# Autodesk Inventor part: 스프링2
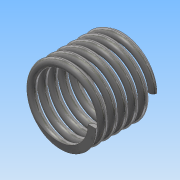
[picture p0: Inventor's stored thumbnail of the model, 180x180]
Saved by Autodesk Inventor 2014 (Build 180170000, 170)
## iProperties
Created: 2019-07
Part Number: 스프링2
Material: 강철, 탄소
Document SubType Name: Modeling
Designer: net
Density: 7.87 g/cm^3
Appearance: 반연마
Mass: 7.71264 g
Surface Area: 20.0054 cm^2
Volume: 0.980005 cm^3
Author: net
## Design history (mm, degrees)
sketch "스케치1"
  geometry: L1 (0, 0)-(8.5, 0); L2 (8.5, 0)-(8.5, -16); L3 (8.5, -16)-(0, -16); L4 (0, -16)-(0, 0); C1 r 1 at (8.5, 0)
  constraints: 8 end point, 2 parallel, 1 centre point, 1 coincident, 1 horizontal, 1 perpendicular
  dimensions: "d0" = 17 diameter of L2 L4; "d1" = 16 distance of L1.end L2.end (derived); "d2" = 2 diameter of C1
feature "코일1" pitch "d3" = 10; turns "d5" = 6; dims "d4" = 16 (= d1), "d6" = 0, angle "d7" = 90 deg, angle "d8" = 90 deg, "d9" = 0, "d10" = 0
node "작업 평면1"
node "작업 평면2"
sketch "스케치2"
  geometry: L1 (-1, 0)-(1, 0) reference; 1 further point
  constraints: 1 horizontal alignment
extrude "돌출1" cut sketch "스케치2" stored distance "d13" = 10; taper "d14" = 0 deg
sketch "스케치3"
  geometry: L1 (7.5, 0)-(9.5, 0) reference; 1 further point
  constraints: 1 horizontal alignment
extrude "돌출2" cut sketch "스케치3" stored distance "d15" = 10; taper "d16" = 0 deg
node "솔리드1"
node "절단 모서리 투영1"
node "절단 모서리 투영2"
other parameters: "d11" = 90 deg, "d12" = 90 deg
